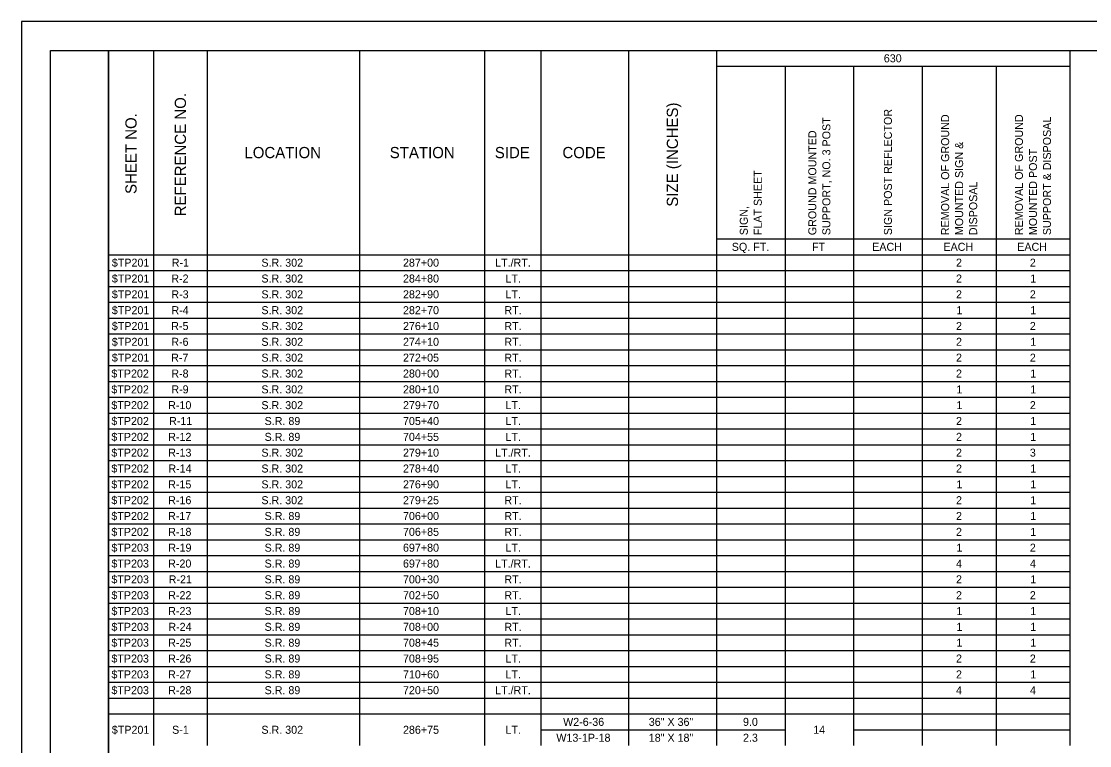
# Model space of a CAD drawing. Extents: x 0 to 34, y 0 to 22.
# Drawn here: x 0 to 18.41, y 9.53 to 22 of the extents above; entities that cross this region are included whole.
import ezdxf

# ---------------------------------------------------------------- set-up
doc = ezdxf.new("R2010")
doc.units = 0
for name, color, linetype in [('SH_Border', 7, 'Continuous'), ('SH_Cut_Line', 7, 'Continuous'), ('SH_Data', 7, 'Continuous'), ('SH_Text', 7, 'Continuous')]:
    doc.layers.add(name, color=color, linetype=linetype)

msp = doc.modelspace()

# ---------------------------------------------------------------- linework, layer by layer
at = {"layer": 'SH_Border'}
for points in [[(0.5, 21.5), (1.5, 21.5), (1.5, 0.5), (0.5, 0.5)], [(1.5, 21.5), (33.5, 21.5), (33.5, 0.5), (1.5, 0.5)]]:
    msp.add_lwpolyline(points, close=True, dxfattribs=at)
at = {"layer": 'SH_Cut_Line'}
msp.add_lwpolyline([(0, 0), (34, 0), (34, 22), (0, 22)], close=True, dxfattribs=at)
at = {"layer": 'SH_Data'}
for p, q in [((1.5, 21.5), (3.201, 21.5)), ((1.5, 21.5), (1.5, 20.682)), ((2.279, 21.5), (2.279, 20.682)), ((3.201, 21.5), (7.98, 21.5)), ((3.201, 21.5), (3.201, 20.682)), ((5.825, 21.5), (5.825, 20.682)), ((7.98, 21.5), (10.461, 21.5)), ((7.98, 21.5), (7.98, 20.682)), ((8.954, 21.5), (8.954, 20.682)), ((10.461, 21.5), (13.162, 21.5)), ((10.461, 21.5), (10.461, 20.682)), ((11.98, 21.5), (11.98, 20.682)), ((13.162, 21.5), (14.344, 21.5)), ((14.344, 21.5), (18.071, 21.5)), ((18.071, 21.5), (18.071, 20.682)), ((11.98, 21.227), (13.162, 21.227)), ((13.162, 21.227), (14.344, 21.227)), ((13.162, 21.227), (13.162, 20.682)), ((14.344, 21.227), (18.071, 21.227)), ((14.344, 21.227), (14.344, 20.682)), ((15.526, 21.227), (15.526, 20.682)), ((16.799, 21.227), (16.799, 20.682)), ((1.5, 20.682), (1.5, 19.63)), ((2.279, 20.682), (2.279, 19.63)), ((3.201, 20.682), (3.201, 19.63)), ((5.825, 20.682), (5.825, 19.63)), ((7.98, 20.682), (7.98, 19.63)), ((8.954, 20.682), (8.954, 19.63)), ((10.461, 20.682), (10.461, 19.63)), ((11.98, 20.682), (11.98, 19.63)), ((13.162, 20.682), (13.162, 19.63)), ((14.344, 20.682), (14.344, 19.63)), ((15.526, 20.682), (15.526, 19.63)), ((16.799, 20.682), (16.799, 19.63)), ((18.071, 20.682), (18.071, 19.63)), ((1.5, 19.63), (1.5, 18.539)), ((2.279, 19.63), (2.279, 18.539)), ((3.201, 19.63), (3.201, 18.539)), ((5.825, 19.63), (5.825, 18.539)), ((7.98, 19.63), (7.98, 18.539)), ((8.954, 19.63), (8.954, 18.539)), ((10.461, 19.63), (10.461, 18.539)), ((11.98, 19.63), (11.98, 18.539)), ((13.162, 19.63), (13.162, 18.539)), ((14.344, 19.63), (14.344, 18.539)), ((15.526, 19.63), (15.526, 18.539)), ((16.799, 19.63), (16.799, 18.539)), ((18.071, 19.63), (18.071, 18.539)), ((1.5, 18.539), (1.5, 18.253)), ((2.279, 18.539), (2.279, 18.253)), ((3.201, 18.539), (3.201, 18.253)), ((5.825, 18.539), (5.825, 18.253)), ((7.98, 18.539), (7.98, 18.253)), ((8.954, 18.539), (8.954, 18.253)), ((10.461, 18.539), (10.461, 18.253)), ((11.98, 18.539), (11.98, 18.253)), ((13.162, 18.539), (13.162, 18.253)), ((14.344, 18.539), (14.344, 18.253)), ((15.526, 18.539), (15.526, 18.253)), ((16.799, 18.539), (16.799, 18.253)), ((18.071, 18.539), (18.071, 18.253)), ((1.5, 18.253), (1.5, 15.799)), ((2.279, 18.253), (2.279, 15.799)), ((3.201, 18.253), (3.201, 15.799)), ((5.825, 18.253), (5.825, 15.799)), ((7.98, 18.253), (7.98, 15.799)), ((8.954, 18.253), (8.954, 15.799)), ((10.461, 18.253), (10.461, 15.799)), ((11.98, 18.253), (13.162, 18.253)), ((11.98, 18.253), (11.98, 15.799)), ((13.162, 18.253), (14.344, 18.253)), ((13.162, 18.253), (13.162, 15.799)), ((14.344, 18.253), (18.071, 18.253)), ((14.344, 18.253), (14.344, 15.799)), ((15.526, 18.253), (15.526, 15.799)), ((16.799, 18.253), (16.799, 15.799)), ((18.071, 18.253), (18.071, 15.799)), ((1.5, 17.981), (3.201, 17.981)), ((3.201, 17.981), (7.98, 17.981)), ((7.98, 17.981), (10.461, 17.981)), ((10.461, 17.981), (13.162, 17.981)), ((13.162, 17.981), (14.344, 17.981)), ((14.344, 17.981), (18.071, 17.981)), ((1.5, 17.708), (3.201, 17.708)), ((3.201, 17.708), (7.98, 17.708)), ((7.98, 17.708), (10.461, 17.708)), ((10.461, 17.708), (13.162, 17.708)), ((13.162, 17.708), (14.344, 17.708)), ((14.344, 17.708), (18.071, 17.708)), ((1.5, 17.435), (3.201, 17.435)), ((3.201, 17.435), (7.98, 17.435)), ((7.98, 17.435), (10.461, 17.435)), ((10.461, 17.435), (13.162, 17.435)), ((13.162, 17.435), (14.344, 17.435)), ((14.344, 17.435), (18.071, 17.435)), ((1.5, 17.162), (3.201, 17.162)), ((3.201, 17.162), (7.98, 17.162)), ((7.98, 17.162), (10.461, 17.162)), ((10.461, 17.162), (13.162, 17.162)), ((13.162, 17.162), (14.344, 17.162)), ((14.344, 17.162), (18.071, 17.162)), ((1.5, 16.89), (3.201, 16.89)), ((3.201, 16.89), (7.98, 16.89)), ((7.98, 16.89), (10.461, 16.89)), ((10.461, 16.89), (13.162, 16.89)), ((13.162, 16.89), (14.344, 16.89)), ((14.344, 16.89), (18.071, 16.89)), ((1.5, 16.617), (3.201, 16.617)), ((3.201, 16.617), (7.98, 16.617)), ((7.98, 16.617), (10.461, 16.617)), ((10.461, 16.617), (13.162, 16.617)), ((13.162, 16.617), (14.344, 16.617)), ((14.344, 16.617), (18.071, 16.617)), ((1.5, 16.344), (3.201, 16.344)), ((3.201, 16.344), (7.98, 16.344)), ((7.98, 16.344), (10.461, 16.344)), ((10.461, 16.344), (13.162, 16.344)), ((13.162, 16.344), (14.344, 16.344)), ((14.344, 16.344), (18.071, 16.344)), ((1.5, 16.071), (3.201, 16.071)), ((3.201, 16.071), (7.98, 16.071)), ((7.98, 16.071), (10.461, 16.071)), ((10.461, 16.071), (13.162, 16.071)), ((13.162, 16.071), (14.344, 16.071)), ((14.344, 16.071), (18.071, 16.071)), ((1.5, 15.799), (3.201, 15.799)), ((1.5, 15.799), (1.5, 15.526)), ((2.279, 15.799), (2.279, 15.526)), ((3.201, 15.799), (7.98, 15.799)), ((3.201, 15.799), (3.201, 15.526)), ((5.825, 15.799), (5.825, 15.526)), ((7.98, 15.799), (10.461, 15.799)), ((7.98, 15.799), (7.98, 15.526)), ((8.954, 15.799), (8.954, 15.526)), ((10.461, 15.799), (13.162, 15.799)), ((10.461, 15.799), (10.461, 15.526)), ((11.98, 15.799), (11.98, 15.526)), ((13.162, 15.799), (14.344, 15.799)), ((13.162, 15.799), (13.162, 15.526)), ((14.344, 15.799), (18.071, 15.799)), ((14.344, 15.799), (14.344, 15.526)), ((15.526, 15.799), (15.526, 15.526)), ((16.799, 15.799), (16.799, 15.526)), ((18.071, 15.799), (18.071, 15.526)), ((1.5, 15.526), (3.201, 15.526)), ((1.5, 15.526), (1.5, 15.253)), ((2.279, 15.526), (2.279, 15.253)), ((3.201, 15.526), (7.98, 15.526)), ((3.201, 15.526), (3.201, 15.253)), ((5.825, 15.526), (5.825, 15.253)), ((7.98, 15.526), (10.461, 15.526)), ((7.98, 15.526), (7.98, 15.253)), ((8.954, 15.526), (8.954, 15.253)), ((10.461, 15.526), (13.162, 15.526)), ((10.461, 15.526), (10.461, 15.253)), ((11.98, 15.526), (11.98, 15.253)), ((13.162, 15.526), (14.344, 15.526)), ((13.162, 15.526), (13.162, 15.253)), ((14.344, 15.526), (18.071, 15.526)), ((14.344, 15.526), (14.344, 15.253)), ((15.526, 15.526), (15.526, 15.253)), ((16.799, 15.526), (16.799, 15.253)), ((18.071, 15.526), (18.071, 15.253)), ((1.5, 15.253), (3.201, 15.253)), ((1.5, 15.253), (1.5, 14.981)), ((2.279, 15.253), (2.279, 14.981)), ((3.201, 15.253), (7.98, 15.253)), ((3.201, 15.253), (3.201, 14.981)), ((5.825, 15.253), (5.825, 14.981)), ((7.98, 15.253), (10.461, 15.253)), ((7.98, 15.253), (7.98, 14.981)), ((8.954, 15.253), (8.954, 14.981)), ((10.461, 15.253), (13.162, 15.253)), ((10.461, 15.253), (10.461, 14.981)), ((11.98, 15.253), (11.98, 14.981)), ((13.162, 15.253), (14.344, 15.253)), ((13.162, 15.253), (13.162, 14.981)), ((14.344, 15.253), (18.071, 15.253)), ((14.344, 15.253), (14.344, 14.981)), ((15.526, 15.253), (15.526, 14.981)), ((16.799, 15.253), (16.799, 14.981)), ((18.071, 15.253), (18.071, 14.981)), ((1.5, 14.981), (3.201, 14.981)), ((1.5, 14.981), (1.5, 14.435)), ((2.279, 14.981), (2.279, 14.435)), ((3.201, 14.981), (7.98, 14.981)), ((3.201, 14.981), (3.201, 14.435)), ((5.825, 14.981), (5.825, 14.435)), ((7.98, 14.981), (10.461, 14.981)), ((7.98, 14.981), (7.98, 14.435)), ((8.954, 14.981), (8.954, 14.435)), ((10.461, 14.981), (13.162, 14.981)), ((10.461, 14.981), (10.461, 14.435)), ((11.98, 14.981), (11.98, 14.435)), ((13.162, 14.981), (14.344, 14.981)), ((13.162, 14.981), (13.162, 14.435)), ((14.344, 14.981), (18.071, 14.981)), ((14.344, 14.981), (14.344, 14.435)), ((15.526, 14.981), (15.526, 14.435)), ((16.799, 14.981), (16.799, 14.435)), ((18.071, 14.981), (18.071, 14.435)), ((1.5, 14.708), (3.201, 14.708)), ((3.201, 14.708), (7.98, 14.708)), ((7.98, 14.708), (10.461, 14.708)), ((10.461, 14.708), (13.162, 14.708)), ((13.162, 14.708), (14.344, 14.708)), ((14.344, 14.708), (18.071, 14.708)), ((1.5, 14.435), (3.201, 14.435)), ((1.5, 14.435), (1.5, 14.162)), ((2.279, 14.435), (2.279, 14.162)), ((3.201, 14.435), (7.98, 14.435)), ((3.201, 14.435), (3.201, 14.162)), ((5.825, 14.435), (5.825, 14.162)), ((7.98, 14.435), (10.461, 14.435)), ((7.98, 14.435), (7.98, 14.162)), ((8.954, 14.435), (8.954, 14.162)), ((10.461, 14.435), (13.162, 14.435)), ((10.461, 14.435), (10.461, 14.162)), ((11.98, 14.435), (11.98, 14.162)), ((13.162, 14.435), (14.344, 14.435)), ((13.162, 14.435), (13.162, 14.162)), ((14.344, 14.435), (18.071, 14.435)), ((14.344, 14.435), (14.344, 14.162)), ((15.526, 14.435), (15.526, 14.162)), ((16.799, 14.435), (16.799, 14.162)), ((18.071, 14.435), (18.071, 14.162)), ((1.5, 14.162), (3.201, 14.162)), ((1.5, 14.162), (1.5, 9.526)), ((2.279, 14.162), (2.279, 9.526)), ((3.201, 14.162), (7.98, 14.162)), ((3.201, 14.162), (3.201, 9.526)), ((5.825, 14.162), (5.825, 9.526)), ((7.98, 14.162), (10.461, 14.162)), ((7.98, 14.162), (7.98, 9.526)), ((8.954, 14.162), (8.954, 9.526)), ((10.461, 14.162), (13.162, 14.162)), ((10.461, 14.162), (10.461, 9.526)), ((11.98, 14.162), (11.98, 9.526)), ((13.162, 14.162), (14.344, 14.162)), ((13.162, 14.162), (13.162, 9.526)), ((14.344, 14.162), (18.071, 14.162)), ((14.344, 14.162), (14.344, 9.526)), ((15.526, 14.162), (15.526, 9.526)), ((16.799, 14.162), (16.799, 9.526)), ((18.071, 14.162), (18.071, 9.526)), ((1.5, 13.89), (3.201, 13.89)), ((3.201, 13.89), (7.98, 13.89)), ((7.98, 13.89), (10.461, 13.89)), ((10.461, 13.89), (13.162, 13.89)), ((13.162, 13.89), (14.344, 13.89)), ((14.344, 13.89), (18.071, 13.89)), ((1.5, 13.617), (3.201, 13.617)), ((3.201, 13.617), (7.98, 13.617)), ((7.98, 13.617), (10.461, 13.617)), ((10.461, 13.617), (13.162, 13.617)), ((13.162, 13.617), (14.344, 13.617)), ((14.344, 13.617), (18.071, 13.617)), ((1.5, 13.344), (3.201, 13.344)), ((3.201, 13.344), (7.98, 13.344)), ((7.98, 13.344), (10.461, 13.344)), ((10.461, 13.344), (13.162, 13.344)), ((13.162, 13.344), (14.344, 13.344)), ((14.344, 13.344), (18.071, 13.344)), ((1.5, 13.072), (3.201, 13.072)), ((3.201, 13.072), (7.98, 13.072)), ((7.98, 13.072), (10.461, 13.072)), ((10.461, 13.072), (13.162, 13.072)), ((13.162, 13.072), (14.344, 13.072)), ((14.344, 13.072), (18.071, 13.072)), ((1.5, 12.799), (3.201, 12.799)), ((3.201, 12.799), (7.98, 12.799)), ((7.98, 12.799), (10.461, 12.799)), ((10.461, 12.799), (13.162, 12.799)), ((13.162, 12.799), (14.344, 12.799)), ((14.344, 12.799), (18.071, 12.799)), ((1.5, 12.526), (3.201, 12.526)), ((3.201, 12.526), (7.98, 12.526)), ((7.98, 12.526), (10.461, 12.526)), ((10.461, 12.526), (13.162, 12.526)), ((13.162, 12.526), (14.344, 12.526)), ((14.344, 12.526), (18.071, 12.526)), ((1.5, 12.253), (3.201, 12.253)), ((3.201, 12.253), (7.98, 12.253)), ((7.98, 12.253), (10.461, 12.253)), ((10.461, 12.253), (13.162, 12.253)), ((13.162, 12.253), (14.344, 12.253)), ((14.344, 12.253), (18.071, 12.253)), ((1.5, 11.981), (3.201, 11.981)), ((3.201, 11.981), (7.98, 11.981)), ((7.98, 11.981), (10.461, 11.981)), ((10.461, 11.981), (13.162, 11.981)), ((13.162, 11.981), (14.344, 11.981)), ((14.344, 11.981), (18.071, 11.981)), ((1.5, 11.708), (3.201, 11.708)), ((3.201, 11.708), (7.98, 11.708)), ((7.98, 11.708), (10.461, 11.708)), ((10.461, 11.708), (13.162, 11.708)), ((13.162, 11.708), (14.344, 11.708)), ((14.344, 11.708), (18.071, 11.708)), ((1.5, 11.435), (3.201, 11.435)), ((3.201, 11.435), (7.98, 11.435)), ((7.98, 11.435), (10.461, 11.435)), ((10.461, 11.435), (13.162, 11.435)), ((13.162, 11.435), (14.344, 11.435)), ((14.344, 11.435), (18.071, 11.435)), ((1.5, 11.162), (3.201, 11.162)), ((3.201, 11.162), (7.98, 11.162)), ((7.98, 11.162), (10.461, 11.162)), ((10.461, 11.162), (13.162, 11.162)), ((13.162, 11.162), (14.344, 11.162)), ((14.344, 11.162), (18.071, 11.162)), ((1.5, 10.89), (3.201, 10.89)), ((3.201, 10.89), (7.98, 10.89)), ((7.98, 10.89), (10.461, 10.89)), ((10.461, 10.89), (13.162, 10.89)), ((13.162, 10.89), (14.344, 10.89)), ((14.344, 10.89), (18.071, 10.89)), ((1.5, 10.617), (3.201, 10.617)), ((3.201, 10.617), (7.98, 10.617)), ((7.98, 10.617), (10.461, 10.617)), ((10.461, 10.617), (13.162, 10.617)), ((13.162, 10.617), (14.344, 10.617)), ((14.344, 10.617), (18.071, 10.617)), ((1.5, 10.344), (3.201, 10.344)), ((3.201, 10.344), (7.98, 10.344)), ((7.98, 10.344), (10.461, 10.344)), ((10.461, 10.344), (13.162, 10.344)), ((13.162, 10.344), (14.344, 10.344)), ((14.344, 10.344), (18.071, 10.344)), ((1.5, 10.072), (3.201, 10.072)), ((3.201, 10.072), (7.98, 10.072)), ((7.98, 10.072), (10.461, 10.072)), ((10.461, 10.072), (13.162, 10.072)), ((13.162, 10.072), (14.344, 10.072)), ((14.344, 10.072), (18.071, 10.072)), ((8.954, 9.799), (10.461, 9.799)), ((10.461, 9.799), (13.162, 9.799)), ((14.344, 9.799), (18.071, 9.799))]:
    msp.add_line(p, q, dxfattribs=at)

# ---------------------------------------------------------------- texts
at = {"layer": 'SH_Text'}
for s, height, p in [('630', 0.138, (14.864, 21.295)), ('LOCATION', 0.1932, (3.844, 19.644)), ('STATION', 0.1932, (6.349, 19.644)), ('SIDE', 0.1932, (8.16, 19.644)), ('CODE', 0.1932, (9.325, 19.644)), ('SQ. FT.', 0.138, (12.244, 18.048)), ('FT', 0.138, (13.626, 18.048)), ('EACH', 0.138, (14.664, 18.048)), ('EACH', 0.138, (15.891, 18.048)), ('EACH', 0.138, (17.164, 18.048)), ('$TP201', 0.138, (1.559, 17.775)), ('R-1', 0.138, (2.592, 17.775)), ('S.R. 302', 0.138, (4.137, 17.775)), ('287+00', 0.138, (6.577, 17.775)), ('LT./RT.', 0.138, (8.165, 17.775)), ('2', 0.138, (16.108, 17.775)), ('2', 0.138, (17.381, 17.775)), ('$TP201', 0.138, (1.559, 17.502)), ('R-2', 0.138, (2.584, 17.502)), ('S.R. 302', 0.138, (4.137, 17.502)), ('284+80', 0.138, (6.577, 17.502)), ('LT.', 0.138, (8.345, 17.502)), ('2', 0.138, (16.108, 17.502)), ('1', 0.138, (17.389, 17.502)), ('$TP201', 0.138, (1.559, 17.23)), ('R-3', 0.138, (2.585, 17.23)), ('S.R. 302', 0.138, (4.137, 17.23)), ('282+90', 0.138, (6.577, 17.23)), ('LT.', 0.138, (8.345, 17.23)), ('2', 0.138, (16.108, 17.23)), ('2', 0.138, (17.381, 17.23)), ('$TP201', 0.138, (1.559, 16.957)), ('R-4', 0.138, (2.586, 16.957)), ('S.R. 302', 0.138, (4.137, 16.957)), ('282+70', 0.138, (6.577, 16.957)), ('RT.', 0.138, (8.324, 16.957)), ('1', 0.138, (16.116, 16.957)), ('1', 0.138, (17.389, 16.957)), ('$TP201', 0.138, (1.559, 16.684)), ('R-5', 0.138, (2.583, 16.684)), ('S.R. 302', 0.138, (4.137, 16.684)), ('276+10', 0.138, (6.577, 16.684)), ('RT.', 0.138, (8.324, 16.684)), ('2', 0.138, (16.108, 16.684)), ('2', 0.138, (17.381, 16.684)), ('$TP201', 0.138, (1.559, 16.412)), ('R-6', 0.138, (2.584, 16.412)), ('S.R. 302', 0.138, (4.137, 16.412)), ('274+10', 0.138, (6.577, 16.412)), ('RT.', 0.138, (8.324, 16.412)), ('2', 0.138, (16.108, 16.412)), ('1', 0.138, (17.389, 16.412)), ('$TP201', 0.138, (1.559, 16.139)), ('R-7', 0.138, (2.581, 16.139)), ('S.R. 302', 0.138, (4.137, 16.139)), ('272+05', 0.138, (6.577, 16.139)), ('RT.', 0.138, (8.324, 16.139)), ('2', 0.138, (16.108, 16.139)), ('2', 0.138, (17.381, 16.139)), ('$TP202', 0.138, (1.551, 15.866)), ('R-8', 0.138, (2.584, 15.866)), ('S.R. 302', 0.138, (4.137, 15.866)), ('280+00', 0.138, (6.577, 15.866)), ('RT.', 0.138, (8.324, 15.866)), ('2', 0.138, (16.108, 15.866)), ('1', 0.138, (17.389, 15.866)), ('$TP202', 0.138, (1.551, 15.593)), ('R-9', 0.138, (2.585, 15.593)), ('S.R. 302', 0.138, (4.137, 15.593)), ('280+10', 0.138, (6.577, 15.593)), ('RT.', 0.138, (8.324, 15.593)), ('1', 0.138, (16.116, 15.593)), ('1', 0.138, (17.389, 15.593)), ('$TP202', 0.138, (1.551, 15.321)), ('R-10', 0.138, (2.53, 15.321)), ('S.R. 302', 0.138, (4.137, 15.321)), ('279+70', 0.138, (6.577, 15.321)), ('LT.', 0.138, (8.345, 15.321)), ('1', 0.138, (16.116, 15.321)), ('2', 0.138, (17.381, 15.321)), ('$TP202', 0.138, (1.551, 15.048)), ('R-11', 0.138, (2.546, 15.048)), ('S.R. 89', 0.138, (4.192, 15.048)), ('705+40', 0.138, (6.577, 15.048)), ('LT.', 0.138, (8.345, 15.048)), ('2', 0.138, (16.108, 15.048)), ('1', 0.138, (17.389, 15.048)), ('$TP202', 0.138, (1.551, 14.775)), ('R-12', 0.138, (2.531, 14.775)), ('S.R. 89', 0.138, (4.192, 14.775)), ('704+55', 0.138, (6.577, 14.775)), ('LT.', 0.138, (8.345, 14.775)), ('2', 0.138, (16.108, 14.775)), ('1', 0.138, (17.389, 14.775)), ('$TP202', 0.138, (1.551, 14.503)), ('R-13', 0.138, (2.531, 14.503)), ('S.R. 302', 0.138, (4.137, 14.503)), ('279+10', 0.138, (6.577, 14.503)), ('LT./RT.', 0.138, (8.165, 14.503)), ('2', 0.138, (16.108, 14.503)), ('3', 0.138, (17.381, 14.503)), ('$TP202', 0.138, (1.551, 14.23)), ('R-14', 0.138, (2.533, 14.23)), ('S.R. 302', 0.138, (4.137, 14.23)), ('278+40', 0.138, (6.577, 14.23)), ('LT.', 0.138, (8.345, 14.23)), ('2', 0.138, (16.108, 14.23)), ('1', 0.138, (17.389, 14.23)), ('$TP202', 0.138, (1.551, 13.957)), ('R-15', 0.138, (2.53, 13.957)), ('S.R. 302', 0.138, (4.137, 13.957)), ('276+90', 0.138, (6.577, 13.957)), ('LT.', 0.138, (8.345, 13.957)), ('1', 0.138, (16.116, 13.957)), ('1', 0.138, (17.389, 13.957)), ('$TP202', 0.138, (1.551, 13.684)), ('R-16', 0.138, (2.53, 13.684)), ('S.R. 302', 0.138, (4.137, 13.684)), ('279+25', 0.138, (6.577, 13.684)), ('RT.', 0.138, (8.324, 13.684)), ('2', 0.138, (16.108, 13.684)), ('1', 0.138, (17.389, 13.684)), ('$TP202', 0.138, (1.551, 13.412)), ('R-17', 0.138, (2.528, 13.412)), ('S.R. 89', 0.138, (4.192, 13.412)), ('706+00', 0.138, (6.577, 13.412)), ('RT.', 0.138, (8.324, 13.412)), ('2', 0.138, (16.108, 13.412)), ('1', 0.138, (17.389, 13.412)), ('$TP202', 0.138, (1.551, 13.139)), ('R-18', 0.138, (2.531, 13.139)), ('S.R. 89', 0.138, (4.192, 13.139)), ('706+85', 0.138, (6.577, 13.139)), ('RT.', 0.138, (8.324, 13.139)), ('2', 0.138, (16.108, 13.139)), ('1', 0.138, (17.389, 13.139)), ('$TP203', 0.138, (1.552, 12.866)), ('R-19', 0.138, (2.532, 12.866)), ('S.R. 89', 0.138, (4.192, 12.866)), ('697+80', 0.138, (6.577, 12.866)), ('LT.', 0.138, (8.345, 12.866)), ('1', 0.138, (16.116, 12.866)), ('2', 0.138, (17.381, 12.866)), ('$TP203', 0.138, (1.552, 12.593)), ('R-20', 0.138, (2.53, 12.593)), ('S.R. 89', 0.138, (4.192, 12.593)), ('697+80', 0.138, (6.577, 12.593)), ('LT./RT.', 0.138, (8.165, 12.593)), ('4', 0.138, (16.11, 12.593)), ('4', 0.138, (17.383, 12.593)), ('$TP203', 0.138, (1.552, 12.321)), ('R-21', 0.138, (2.539, 12.321)), ('S.R. 89', 0.138, (4.192, 12.321)), ('700+30', 0.138, (6.577, 12.321)), ('RT.', 0.138, (8.324, 12.321)), ('2', 0.138, (16.108, 12.321)), ('1', 0.138, (17.389, 12.321)), ('$TP203', 0.138, (1.552, 12.048)), ('R-22', 0.138, (2.531, 12.048)), ('S.R. 89', 0.138, (4.192, 12.048)), ('702+50', 0.138, (6.577, 12.048)), ('RT.', 0.138, (8.324, 12.048)), ('2', 0.138, (16.108, 12.048)), ('2', 0.138, (17.381, 12.048)), ('$TP203', 0.138, (1.552, 11.775)), ('R-23', 0.138, (2.531, 11.775)), ('S.R. 89', 0.138, (4.192, 11.775)), ('708+10', 0.138, (6.577, 11.775)), ('LT.', 0.138, (8.345, 11.775)), ('1', 0.138, (16.116, 11.775)), ('1', 0.138, (17.389, 11.775)), ('$TP203', 0.138, (1.552, 11.503)), ('R-24', 0.138, (2.533, 11.503)), ('S.R. 89', 0.138, (4.192, 11.503)), ('708+00', 0.138, (6.577, 11.503)), ('RT.', 0.138, (8.324, 11.503)), ('1', 0.138, (16.116, 11.503)), ('1', 0.138, (17.389, 11.503)), ('$TP203', 0.138, (1.552, 11.23)), ('R-25', 0.138, (2.53, 11.23)), ('S.R. 89', 0.138, (4.192, 11.23)), ('708+45', 0.138, (6.577, 11.23)), ('RT.', 0.138, (8.324, 11.23)), ('1', 0.138, (16.116, 11.23)), ('1', 0.138, (17.389, 11.23)), ('$TP203', 0.138, (1.552, 10.957)), ('R-26', 0.138, (2.53, 10.957)), ('S.R. 89', 0.138, (4.192, 10.957)), ('708+95', 0.138, (6.577, 10.957)), ('LT.', 0.138, (8.345, 10.957)), ('2', 0.138, (16.108, 10.957)), ('2', 0.138, (17.381, 10.957)), ('$TP203', 0.138, (1.552, 10.684)), ('R-27', 0.138, (2.528, 10.684)), ('S.R. 89', 0.138, (4.192, 10.684)), ('710+60', 0.138, (6.577, 10.684)), ('LT.', 0.138, (8.345, 10.684)), ('2', 0.138, (16.108, 10.684)), ('1', 0.138, (17.389, 10.684)), ('$TP203', 0.138, (1.552, 10.412)), ('R-28', 0.138, (2.531, 10.412)), ('S.R. 89', 0.138, (4.192, 10.412)), ('720+50', 0.138, (6.577, 10.412)), ('LT./RT.', 0.138, (8.165, 10.412)), ('4', 0.138, (16.11, 10.412)), ('4', 0.138, (17.383, 10.412)), ('W2-6-36', 0.138, (9.337, 9.866)), ('36" X 36"', 0.138, (10.813, 9.866)), ('9.0', 0.138, (12.437, 9.866)), ('$TP201', 0.138, (1.559, 9.73)), ('S-1', 0.138, (2.598, 9.73)), ('S.R. 302', 0.138, (4.137, 9.73)), ('286+75', 0.138, (6.577, 9.73)), ('LT.', 0.138, (8.345, 9.73)), ('14', 0.138, (13.647, 9.73)), ('W13-1P-18', 0.138, (9.22, 9.593)), ('18" X 18"', 0.138, (10.813, 9.593)), ('2.3', 0.138, (12.437, 9.593))]:
    msp.add_text(s, height=height, dxfattribs=at).set_placement(p)
for s, height, p in [('REFERENCE NO.', 0.19318, (2.837, 18.642)), ('SIZE (INCHES)', 0.19318, (11.317, 18.808)), ('SIGN POST REFLECTOR', 0.13799, (15.004, 18.318)), ('SHEET NO.', 0.1932, (1.986, 19.027)), ('SUPPORT, NO. 3 POST', 0.13799, (13.943, 18.318)), ('REMOVAL OF GROUND ', 0.13799, (15.99, 18.318)), ('REMOVAL OF GROUND', 0.13799, (17.262, 18.318)), ('SUPPORT & DISPOSAL', 0.13799, (17.745, 18.318)), ('GROUND MOUNTED', 0.13799, (13.701, 18.318)), ('MOUNTED SIGN &', 0.13799, (16.231, 18.318)), ('MOUNTED POST', 0.13799, (17.504, 18.318)), ('FLAT SHEET', 0.138, (12.761, 18.318)), ('DISPOSAL', 0.138, (16.473, 18.318)), ('SIGN, ', 0.138, (12.52, 18.318))]:
    msp.add_text(s, height=height, rotation=90, dxfattribs=at).set_placement(p)

doc.saveas('drawing.dxf')
